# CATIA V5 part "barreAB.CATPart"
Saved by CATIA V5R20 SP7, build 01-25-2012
Part number: barreAB
Publications: "pivot_AB_base", "pivot_AB_CE", "Plan_Ref"
Bounding box of the stored display mesh (mm): x -15 to 23, y 285.004 to 350.087, z 171.37 to 294.989
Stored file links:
  G:\IAO\apres\barreAB.CATPart
  G:\IAO\apres\psedsuay.CATProduct
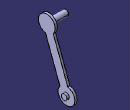
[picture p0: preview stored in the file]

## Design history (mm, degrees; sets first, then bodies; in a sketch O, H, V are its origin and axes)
External parameters (linked from other documents)
  External.Longueur_AB = 100 mm
  External.Diametre = 30 mm
  External.Largeur = 15 mm
  External.Epaisseur = 4 mm
  External.Diametre_pivot = 10 mm
Set1
  Point1 "Point_A": linked copy from another document
  Point2 "Point_B": linked copy from another document
  Plane1 "Plan_Ref": linked copy from another document
Set2 "skelette"
  Line1 "Barra_AB": type PtPt, FirstPoint Point1, SecondPoint Point2
  Line2 "pivot_AB_base": type Normal, RefPoint Point1, RefSkin Plane1, Start -20, End 20
  Line3 "pivot_AB_CE": type Normal, RefPoint Point2, RefSkin Plane1, Start -20, End 20
Set3 "piece"
  Plane2: type OffsetPt, RefPlane yz-plane, RefPoint Point1
  Plane3: type Offset, RefPlane Plane2, Offset 15 {= 0.15*External.Longueur_AB}
  Sketch1 on Plane3, origin (15, 0, 0), H (0, 1, 0), V (0, 0, 1)
    arc A1 centre (300, 280) radius 15 from (311.5815, 270.4675) to (297.5353, 265.2039) ccw
    arc A2 centre (335.0906, 186.3589) radius 15 from (323.5091, 195.8915) to (337.5552, 201.155) ccw
    line L1 (297.5353, 265.2039) -> (323.5091, 195.8915)
    line L2 (311.5815, 270.4675) -> (337.5552, 201.155)
    reference projected point E1 (300, 280) from Line2
    reference projected point E2 (335.0906, 186.3589) from Line3
    construction line L3 (300, 280) -> (335.0906, 186.3589)
    radius A1 = 15 {= External.Diametre /2}
    radius A2 = 15 {= External.Diametre /2}
    distance L2 L1 = 15 {= External.Largeur}
    concentricity: A1 E1, A2 E2
    symmetry: L2 L1 L3
  Plane4: type Offset, RefPlane Plane3, Offset 4 {= External.Epaisseur}
  Sketch2 on Plane3, origin (15, 0, 0), H (0, 1, 0), V (0, 0, 1)
    circle A1 centre (300, 280) radius 5
    reference projected point E1 (300, 280) from Line2
    radius A1 = 5 {= External.Diametre_pivot /2}
    concentricity: A1 E1
  Sketch3 on Plane4, origin (19, 0, 0), H (0, 1, 0), V (0, 0, 1)
    circle A1 centre (335.0906, 186.3589) radius 5
    reference projected point E1 (335.0906, 186.3589) from Line3
    radius A1 = 5 {= External.Diametre_pivot /2}
    concentricity: A1 E1
Body1 (main body)
  Pad1: profile Sketch1, direction (1, 0, 0), length 4 {= External.Epaisseur}
  Pad2: profile Sketch2, direction (-1, 0, 0), length 30 {= 0.3*External.Longueur_AB}
  Pad3: profile Sketch3, direction (1, 0, 0), length 4 {= External.Epaisseur}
